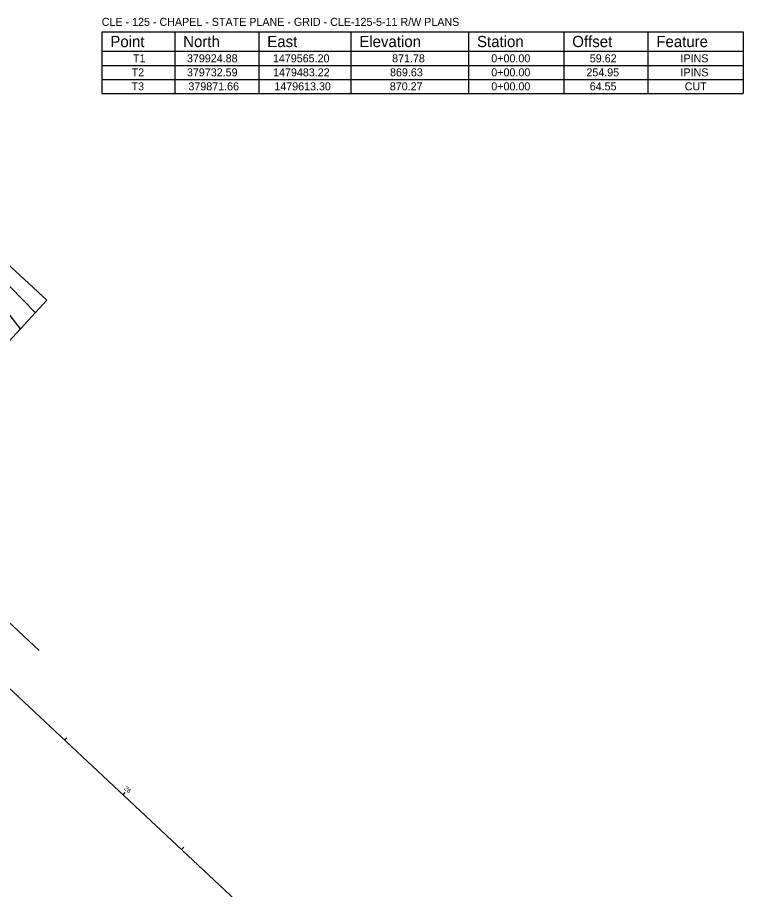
# Model space of a CAD drawing. Extents: x 1474076 to 1484331, y 375914 to 383395.
# Drawn here: x 1479954 to 1480414, y 379506 to 380051 of the extents above; entities that cross this region are included whole.
import ezdxf

# ---------------------------------------------------------------- set-up
doc = ezdxf.new("R2010")
doc.units = 0
for name, color, linetype in [('Default', 7, 'Continuous'), ('DV_X_Property_Line', 7, 'Continuous'), ('RW_X_CL_20', 7, 'Continuous'), ('RW_X_Esmt_SH', 7, 'Continuous'), ('RW_X_Esmt_U', 7, 'Continuous'), ('SV_X_Text', 7, 'Continuous')]:
    doc.layers.add(name, color=color, linetype=linetype)

msp = doc.modelspace()

# ---------------------------------------------------------------- linework, layer by layer
at = {"layer": 'Default'}
for p, q in [((1480006.61, 380041.98), (1480407.11, 380041.98)), ((1480006.61, 380041.98), (1480006.61, 380003.48)), ((1480052.11, 380041.98), (1480052.11, 380003.48)), ((1480104.61, 380041.98), (1480104.61, 380003.48)), ((1480162.11, 380041.98), (1480162.11, 380003.48)), ((1480235.61, 380041.98), (1480235.61, 380003.48)), ((1480295.11, 380041.98), (1480295.11, 380003.48)), ((1480347.61, 380041.98), (1480347.61, 380003.48)), ((1480407.11, 380041.98), (1480407.11, 380003.48)), ((1480407.11, 380041.98), (1480407.11, 380003.48)), ((1480006.61, 380029.73), (1480407.11, 380029.73)), ((1480006.61, 380020.98), (1480407.11, 380020.98)), ((1480006.61, 380020.98), (1480407.11, 380020.98)), ((1480006.61, 380020.98), (1480407.11, 380020.98)), ((1480006.61, 380020.98), (1480407.11, 380020.98)), ((1480006.61, 380020.98), (1480407.11, 380020.98)), ((1480006.61, 380020.98), (1480407.11, 380020.98)), ((1480006.61, 380020.98), (1480407.11, 380020.98)), ((1480006.61, 380012.23), (1480407.11, 380012.23)), ((1480006.61, 380012.23), (1480407.11, 380012.23)), ((1480006.61, 380012.23), (1480407.11, 380012.23)), ((1480006.61, 380012.23), (1480407.11, 380012.23)), ((1480006.61, 380012.23), (1480407.11, 380012.23)), ((1480006.61, 380012.23), (1480407.11, 380012.23)), ((1480006.61, 380012.23), (1480407.11, 380012.23)), ((1480006.61, 380003.48), (1480407.11, 380003.48)), ((1480006.61, 380003.48), (1480407.11, 380003.48)), ((1480006.61, 380003.48), (1480407.11, 380003.48)), ((1480006.61, 380003.48), (1480407.11, 380003.48)), ((1480006.61, 380003.48), (1480407.11, 380003.48)), ((1480006.61, 380003.48), (1480407.11, 380003.48)), ((1480006.61, 380003.48), (1480407.11, 380003.48))]:
    msp.add_line(p, q, dxfattribs=at)
at = {"layer": 'DV_X_Property_Line'}
for p, q in [((1479917.96, 379924.35), (1479972.23, 379874.23)), ((1479955.72, 379856.37), (1479909.79, 379915.51)), ((1479936.32, 379907.39), (1479972.23, 379874.23)), ((1479972.23, 379874.23), (1479842.89, 379734.31)), ((1479972.23, 379874.23), (1479955.72, 379856.37))]:
    msp.add_line(p, q, dxfattribs=at)
at = {"layer": 'RW_X_CL_20'}
for p, q in [((1479566.7, 379989.54), (1480555.97, 379063.33)), ((1479983.31, 379599.48), (1479984.68, 379600.94)), ((1480019.81, 379565.31), (1480021.18, 379566.77)), ((1480056.31, 379531.14), (1480057.68, 379532.6))]:
    msp.add_line(p, q, dxfattribs=at)
at = {"layer": 'RW_X_Esmt_SH'}
msp.add_line((1479687.35, 379917.68), (1479967.32, 379655.56), dxfattribs=at)
at = {"layer": 'RW_X_Esmt_U'}
msp.add_line((1479825.48, 380008.52), (1479965.05, 379866.47), dxfattribs=at)

# ---------------------------------------------------------------- texts
at = {"layer": 'Default'}
for s, height, p in [('Point', 7, (1480011.86, 380032.36)), ('North', 7, (1480057.36, 380032.36)), ('East', 7, (1480109.86, 380032.36)), ('Elevation', 7, (1480167.36, 380032.36)), ('Station', 7, (1480240.86, 380032.36)), ('Offset', 7, (1480300.36, 380032.36)), ('Feature', 7, (1480352.86, 380032.36)), ('T1', 5, (1480025.98, 380022.86)), ('379924.88', 5, (1480059.72, 380022.86)), ('1479565.20', 5, (1480113.4, 380022.86)), ('871.78', 5, (1480187.84, 380022.86)), ('0+00.00', 5, (1480249.79, 380022.86)), ('59.62', 5, (1480311.3, 380022.86)), ('IPINS', 5, (1480367.95, 380022.86)), ('T2', 5, (1480025.15, 380014.11)), ('379732.59', 5, (1480059.7, 380014.11)), ('1479483.22', 5, (1480113.5, 380014.11)), ('869.63', 5, (1480186.54, 380014.11)), ('0+00.00', 5, (1480249.79, 380014.11)), ('254.95', 5, (1480309.16, 380014.11)), ('IPINS', 5, (1480367.95, 380014.11)), ('T3', 5, (1480025.09, 380005.36)), ('379871.66', 5, (1480060.61, 380005.36)), ('1479613.30', 5, (1480114.27, 380005.36)), ('870.27', 5, (1480186.4, 380005.36)), ('0+00.00', 5, (1480249.79, 380005.36)), ('64.55', 5, (1480311.28, 380005.36)), ('CUT', 5, (1480370.59, 380005.36))]:
    msp.add_text(s, height=height, dxfattribs=at).set_placement(p)
at = {"layer": 'RW_X_CL_20'}
msp.add_text('26', height=2.8, rotation=316.8859, dxfattribs=at).set_placement((1480020.2, 379569.05))
at = {"layer": 'SV_X_Text'}
msp.add_text('CLE - 125 - CHAPEL - STATE PLANE - GRID - CLE-125-5-11 R/W PLANS', height=5, dxfattribs=at).set_placement((1480006.49, 380045.63))

doc.saveas('drawing.dxf')
